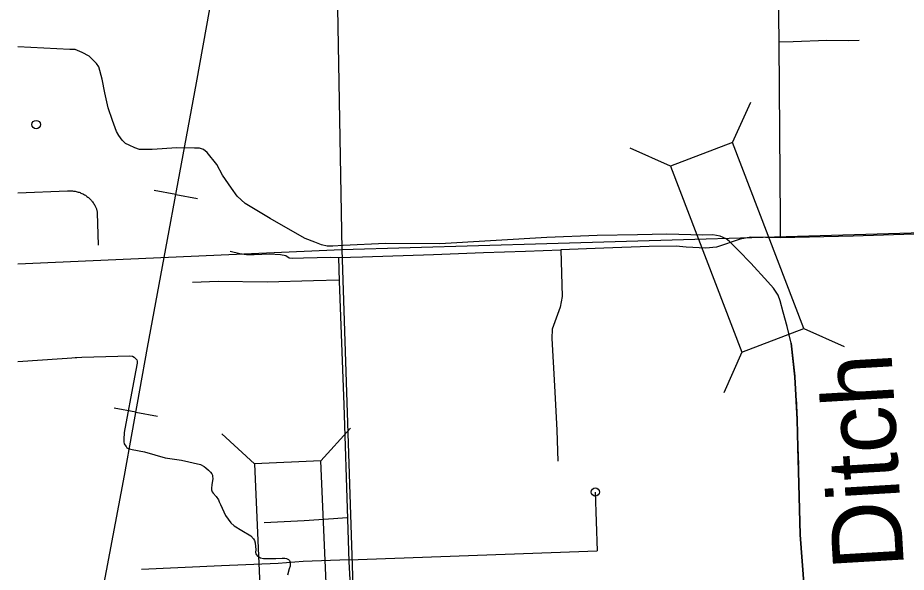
# Model space of a CAD drawing. Extents: x 646058 to 725608, y 1473014 to 1561048.
# Drawn here: x 649176 to 651826, y 1546529 to 1548182 of the extents above; entities that cross this region are included whole.
import ezdxf

# ---------------------------------------------------------------- set-up
doc = ezdxf.new("R2010")
doc.units = 0
doc.layers.add('Default', color=7, linetype='Continuous')

msp = doc.modelspace()

# ---------------------------------------------------------------- linework, layer by layer
at = {"layer": 'Default'}
for p, q in [((651308, 1547810.6), (651361.8, 1547931.1)), ((651123, 1547739.9), (651002.5, 1547793.8)), ((649647.4, 1547655.5), (649582.5, 1547667.6)), ((649647.4, 1547655.5), (649712.2, 1547643.5)), ((651520.1, 1547255.8), (651640.6, 1547201.9)), ((651335.2, 1547185.1), (651281.3, 1547064.6)), ((649528, 1547006.4), (649463, 1547018)), ((649528, 1547006.4), (649593, 1546994.8)), ((649881.8, 1546852.5), (649784.4, 1546941.6)), ((650079.6, 1546861.2), (650168.7, 1546958.6))]:
    msp.add_line(p, q, dxfattribs=at)
for points in [[(649175.8, 1545065), (649314.1, 1545833.5), (649350.5, 1546038), (649406.5, 1546354.4), (649494.3, 1546817.8), (649562.4, 1547199.4), (649709.3, 1547988.3), (649748.7, 1548209.4), (649833.5, 1548683.4), (649871.3, 1548892.3), (649900.1, 1549034.7), (649933.4, 1549177), (649968.2, 1549296.7), (650012.1, 1549423.8), (650066.6, 1549561.6), (650130.2, 1549701), (650202.9, 1549832.7), (650295.2, 1549988.7), (650361.8, 1550099.6)], [(649175.8, 1545065), (649314.1, 1545833.5), (649350.5, 1546038), (649406.5, 1546354.4), (649494.3, 1546817.8), (649562.4, 1547199.4), (649709.3, 1547988.3), (649748.7, 1548209.4), (649833.5, 1548683.4), (649871.3, 1548892.3), (649900.1, 1549034.7), (649933.4, 1549177), (649968.2, 1549296.7), (650012.1, 1549423.8), (650066.6, 1549561.6), (650130.2, 1549701), (650202.9, 1549832.7), (650295.2, 1549988.7), (650361.8, 1550099.6)], [(650076.7, 1550115.4), (650106.2, 1549484.7), (650142.8, 1547491.6)], [(651441.4, 1548452.5), (651445.7, 1548105.6)], [(651441.4, 1548452.5), (651445.7, 1548105.6)], [(649175.8, 1545065), (649314.1, 1545833.5), (649350.5, 1546038), (649406.5, 1546354.4), (649494.3, 1546817.8), (649562.4, 1547199.4), (649709.3, 1547988.3), (649748.7, 1548209.4)], [(651445.6, 1548110.5), (651488.6, 1548112.1), (651588.8, 1548115.4), (651653.6, 1548114.8), (651685.1, 1548115.9)], [(651445.6, 1548110.5), (651488.6, 1548112.1), (651588.8, 1548115.4), (651653.6, 1548114.8), (651685.1, 1548115.9)], [(651482.4, 1547212.5), (651470.3, 1547261.7), (651458.2, 1547304.4), (651449.7, 1547338.6), (651444, 1547355.7), (651429.7, 1547376.3), (651413.4, 1547394.8), (651362.1, 1547451.1), (651325.8, 1547488.9), (651298, 1547516.6), (651288.8, 1547523.8), (651271, 1547530.9), (651248.9, 1547535.1), (651216.9, 1547534.4), (651183.4, 1547535.1), (651111.5, 1547537.3), (651024.7, 1547535.1), (650903.6, 1547533), (650753.4, 1547527.3), (650434.5, 1547508.1), (650272.9, 1547509.5), (650146.2, 1547503.1), (650115.6, 1547501), (650098.5, 1547501), (650082.1, 1547505.9), (650062.2, 1547513.8), (650033, 1547524.5), (649988.8, 1547548.7), (649929, 1547584.3), (649853.6, 1547628.5), (649830.1, 1547650.5), (649813.7, 1547674.7), (649786, 1547713.2), (649769.6, 1547745.3), (649740.4, 1547780.2), (649729.7, 1547789.4), (649718.3, 1547793.7), (649702.7, 1547793.7), (649650.7, 1547795.1), (649576.7, 1547790.1), (649538.9, 1547790.1), (649525.4, 1547794.4), (649507.6, 1547802.2), (649497.6, 1547807.9), (649487.7, 1547817.2), (649477, 1547831.4), (649470.6, 1547843.5), (649458.5, 1547875.6), (649445.7, 1547914.1), (649435.7, 1547958.9), (649427.2, 1547999.5), (649417.2, 1548035.8), (649410.8, 1548046.5), (649399.4, 1548056.5), (649389, 1548067.6), (649367.7, 1548079.3), (649347.1, 1548087.8), (649330.8, 1548088), (649175.8, 1548096)], [(651482.4, 1547212.5), (651470.3, 1547261.7), (651458.2, 1547304.4), (651449.7, 1547338.6), (651444, 1547355.7), (651429.7, 1547376.3), (651413.4, 1547394.8), (651362.1, 1547451.1), (651325.8, 1547488.9), (651298, 1547516.6), (651288.8, 1547523.8), (651271, 1547530.9), (651248.9, 1547535.1), (651216.9, 1547534.4), (651183.4, 1547535.1), (651111.5, 1547537.3), (651024.7, 1547535.1), (650903.6, 1547533), (650753.4, 1547527.3), (650434.5, 1547508.1), (650272.9, 1547509.5), (650146.2, 1547503.1), (650115.6, 1547501), (650098.5, 1547501), (650082.1, 1547505.9), (650062.2, 1547513.8), (650033, 1547524.5), (649988.8, 1547548.7), (649929, 1547584.3), (649853.6, 1547628.5), (649830.1, 1547650.5), (649813.7, 1547674.7), (649786, 1547713.2), (649769.6, 1547745.3), (649740.4, 1547780.2), (649729.7, 1547789.4), (649718.3, 1547793.7), (649702.7, 1547793.7), (649650.7, 1547795.1), (649576.7, 1547790.1), (649538.9, 1547790.1), (649525.4, 1547794.4), (649507.6, 1547802.2), (649497.6, 1547807.9), (649487.7, 1547817.2), (649477, 1547831.4), (649470.6, 1547843.5), (649458.5, 1547875.6), (649445.7, 1547914.1), (649435.7, 1547958.9), (649427.2, 1547999.5), (649417.2, 1548035.8), (649410.8, 1548046.5), (649399.4, 1548056.5), (649389, 1548067.6), (649367.7, 1548079.3), (649347.1, 1548087.8), (649330.8, 1548088), (649175.8, 1548096)], [(651445.7, 1548105.6), (651449.6, 1547579.1), (651449.6, 1547526.6)], [(651445.7, 1548105.6), (651449.6, 1547579.1), (651449.6, 1547526.6)], [(649175.8, 1547448.5), (650142.8, 1547491.6), (652791.8, 1547568.9), (652828.4, 1547570), (654920.6, 1547651.9), (655451.2, 1547664.5), (655464.9, 1547665), (658000, 1547762.6)], [(649175.8, 1547660.4), (649324, 1547666.2), (649326.9, 1547666.4), (649329.9, 1547666.5), (649332.8, 1547666.5), (649335.7, 1547666.4), (649338.7, 1547666.2), (649341.6, 1547665.9), (649344.5, 1547665.5), (649347.4, 1547665), (649350.3, 1547664.4), (649353.2, 1547663.7), (649356, 1547662.9), (649358.8, 1547662), (649361.6, 1547661), (649364.3, 1547659.9), (649367, 1547658.7), (649369.7, 1547657.4), (649372.3, 1547656.1), (649374.9, 1547654.6), (649377.4, 1547653.1), (649379.9, 1547651.5), (649382.3, 1547649.7), (649384.6, 1547648), (649386.9, 1547646.1), (649389.1, 1547644.1), (649391.2, 1547642.1), (649393.3, 1547640), (649395.3, 1547637.8), (649397.2, 1547635.6), (649399.1, 1547633.3), (649400.9, 1547630.9), (649402.5, 1547628.5), (649404.1, 1547626), (649405.7, 1547623.5), (649407.1, 1547620.9), (649408, 1547619), (649408.8, 1547617.1), (649409.6, 1547615.1), (649410.3, 1547613.1), (649410.9, 1547611.1), (649411.4, 1547609), (649411.9, 1547607), (649412.3, 1547604.9), (649412.7, 1547602.8), (649413, 1547600.7), (649416, 1547504)], [(649175.8, 1547660.4), (649324, 1547666.2), (649326.9, 1547666.4), (649329.9, 1547666.5), (649332.8, 1547666.5), (649335.7, 1547666.4), (649338.7, 1547666.2), (649341.6, 1547665.9), (649344.5, 1547665.5), (649347.4, 1547665), (649350.3, 1547664.4), (649353.2, 1547663.7), (649356, 1547662.9), (649358.8, 1547662), (649361.6, 1547661), (649364.3, 1547659.9), (649367, 1547658.7), (649369.7, 1547657.4), (649372.3, 1547656.1), (649374.9, 1547654.6), (649377.4, 1547653.1), (649379.9, 1547651.5), (649382.3, 1547649.7), (649384.6, 1547648), (649386.9, 1547646.1), (649389.1, 1547644.1), (649391.2, 1547642.1), (649393.3, 1547640), (649395.3, 1547637.8), (649397.2, 1547635.6), (649399.1, 1547633.3), (649400.9, 1547630.9), (649402.5, 1547628.5), (649404.1, 1547626), (649405.7, 1547623.5), (649407.1, 1547620.9), (649408, 1547619), (649408.8, 1547617.1), (649409.6, 1547615.1), (649410.3, 1547613.1), (649410.9, 1547611.1), (649411.4, 1547609), (649411.9, 1547607), (649412.3, 1547604.9), (649412.7, 1547602.8), (649413, 1547600.7), (649416, 1547504)], [(652792.5, 1547570.8), (652659.6, 1547567.4), (652245.9, 1547551.5), (652029.4, 1547542.9), (651667.7, 1547531.3), (651449.6, 1547526.6)], [(652792.5, 1547570.8), (652659.6, 1547567.4), (652245.9, 1547551.5), (652029.4, 1547542.9), (651667.7, 1547531.3), (651449.6, 1547526.6)], [(651449.6, 1547526.6), (651361.9, 1547528.2), (651330.9, 1547522), (651259.5, 1547498.7), (651227.6, 1547495.6), (651169.4, 1547498.7), (651139.9, 1547501), (651059.2, 1547500.2), (650923.4, 1547495.6), (650795.4, 1547490.1)], [(651449.6, 1547526.6), (651361.9, 1547528.2), (651330.9, 1547522), (651259.5, 1547498.7), (651227.6, 1547495.6), (651169.4, 1547498.7), (651139.9, 1547501), (651059.2, 1547500.2), (650923.4, 1547495.6), (650795.4, 1547490.1)], [(649809, 1547486.4), (649838.5, 1547479.6), (649858.5, 1547476.4), (649880.5, 1547476.4), (649926.8, 1547478.5), (649959.9, 1547477), (649975.1, 1547473.3), (649985.7, 1547466.4), (649996.7, 1547465.9), (650028.2, 1547466.4), (650109.2, 1547469.1), (650132.1, 1547467.5)], [(649809, 1547486.4), (649838.5, 1547479.6), (649858.5, 1547476.4), (649880.5, 1547476.4), (649926.8, 1547478.5), (649959.9, 1547477), (649975.1, 1547473.3), (649985.7, 1547466.4), (649996.7, 1547465.9), (650028.2, 1547466.4), (650109.2, 1547469.1), (650132.1, 1547467.5)], [(650132.1, 1547467.5), (650204.3, 1547469.6), (650416.2, 1547476.4), (650564.9, 1547482.2), (650690, 1547486.4), (650795.4, 1547490.1)], [(650132.1, 1547467.5), (650204.3, 1547469.6), (650416.2, 1547476.4), (650564.9, 1547482.2), (650690, 1547486.4), (650795.4, 1547490.1)], [(650142.8, 1547491.6), (650228.4, 1544845.7)], [(650795.4, 1547490.1), (650799.4, 1547351.5), (650793.1, 1547319.1), (650769.7, 1547254.4), (650768.8, 1547225.7), (650776.9, 1547084.6), (650784.1, 1546952.5), (650786.8, 1546860.9)], [(650795.4, 1547490.1), (650799.4, 1547351.5), (650793.1, 1547319.1), (650769.7, 1547254.4), (650768.8, 1547225.7), (650776.9, 1547084.6), (650784.1, 1546952.5), (650786.8, 1546860.9)], [(650132.1, 1547467.5), (650134.3, 1547396.8)], [(650132.1, 1547467.5), (650134.3, 1547396.8)], [(650134.2, 1547399.8), (650057.7, 1547398.2), (649919.4, 1547394), (649773.3, 1547396.1), (649697.1, 1547392.9)], [(650134.2, 1547399.8), (650057.7, 1547398.2), (649919.4, 1547394), (649773.3, 1547396.1), (649697.1, 1547392.9)], [(650134.3, 1547396.8), (650147.9, 1547028), (650159.2, 1546688.1)], [(650134.3, 1547396.8), (650147.9, 1547028), (650159.2, 1546688.1)], [(651482.4, 1547212.5), (651482.4, 1547212.5), (651493.6, 1547114.1)], [(651520.9, 1546483.9), (651509.5, 1546641.3), (651504.5, 1546830.8), (651502.3, 1546901.3), (651500.9, 1546984.6), (651493.8, 1547112.1), (651482.4, 1547212.5), (651482.4, 1547212.5)], [(651482.4, 1547212.5), (651482.4, 1547212.5), (651493.8, 1547112.1), (651500.9, 1546984.6), (651502.3, 1546901.3), (651504.5, 1546830.8), (651509.5, 1546641.3), (651520.9, 1546483.9)], [(649175.8, 1547157.3), (649367, 1547170.5), (649509.9, 1547174.4), (649517.6, 1547173.4), (649522.8, 1547170.2), (649527.7, 1547166), (649530.5, 1547162.8), (649531.6, 1547158.6), (649531.6, 1547152.3), (649523.5, 1547110.9), (649493.4, 1546945.5), (649491.9, 1546925.2), (649492.3, 1546918.5), (649493, 1546912.2), (649495.5, 1546908.7), (649499, 1546903.8), (649501.4, 1546900.6), (649504.9, 1546898.2), (649512.6, 1546896.1), (649517.4, 1546895.1)], [(649175.8, 1547157.3), (649367, 1547170.5), (649509.9, 1547174.4), (649517.6, 1547173.4), (649522.8, 1547170.2), (649527.7, 1547166), (649530.5, 1547162.8), (649531.6, 1547158.6), (649531.6, 1547152.3), (649523.5, 1547110.9), (649493.4, 1546945.5), (649491.9, 1546925.2), (649492.3, 1546918.5), (649493, 1546912.2), (649495.5, 1546908.7), (649499, 1546903.8), (649501.4, 1546900.6), (649504.9, 1546898.2), (649512.6, 1546896.1), (649517.4, 1546895.1)], [(649347.1, 1547169.2), (649367, 1547170.5), (649509.9, 1547174.4), (649517.6, 1547173.4), (649522.8, 1547170.2), (649527.7, 1547166), (649530.5, 1547162.8), (649531.6, 1547158.6), (649531.6, 1547152.5)], [(651497.4, 1547048.3), (651500.9, 1546984.6), (651502.3, 1546901.3), (651503.9, 1546850.4)], [(649517.4, 1546895.1), (649554, 1546888), (649615.4, 1546870.1), (649664.2, 1546863.1)], [(649517.4, 1546895.1), (649554, 1546888), (649615.4, 1546870.1), (649664.2, 1546863.1)], [(649664.2, 1546863.1), (649720.7, 1546850.8), (649731.9, 1546844.4), (649737.2, 1546840.2), (649744.5, 1546833.9), (649750.5, 1546827.2), (649754.7, 1546822.7), (649756.5, 1546818.8), (649756.8, 1546814.6), (649757.5, 1546808.6), (649754.7, 1546790), (649753.7, 1546780.2), (649754, 1546774.9), (649755.4, 1546769.3), (649758.2, 1546764.8), (649767.7, 1546754.9), (649774.4, 1546745.5), (649776.5, 1546739.5), (649780.3, 1546731.4), (649795.1, 1546698.1), (649810.9, 1546676.6), (649821.4, 1546667.2), (649843.8, 1546653.5), (649870.5, 1546637.7), (649879.3, 1546628.6), (649882.1, 1546623.6), (649884.2, 1546617), (649884.5, 1546606.4), (649885.6, 1546597), (649885.2, 1546587.8), (649886.3, 1546584.7), (649887.7, 1546580.8), (649890.8, 1546577.3), (649894.7, 1546575.2), (649900, 1546572.7), (649909.1, 1546570.6), (649931.5, 1546570.6), (649945.6, 1546570.6), (649964.2, 1546571.3), (649972.6, 1546571.3), (649977.5, 1546569.9), (649983.5, 1546567.5), (649986.3, 1546564), (649988, 1546556.9), (649988, 1546551.7), (649988, 1546547.5), (649985.6, 1546539.4), (649980.3, 1546520.4)], [(649664.2, 1546863.1), (649720.7, 1546850.8), (649731.9, 1546844.4), (649737.2, 1546840.2), (649744.5, 1546833.9), (649750.5, 1546827.2), (649754.7, 1546822.7), (649756.5, 1546818.8), (649756.8, 1546814.6), (649757.5, 1546808.6), (649754.7, 1546790), (649753.7, 1546780.2), (649754, 1546774.9), (649755.4, 1546769.3), (649758.2, 1546764.8), (649767.7, 1546754.9), (649774.4, 1546745.5), (649776.5, 1546739.5), (649780.3, 1546731.4), (649795.1, 1546698.1), (649810.9, 1546676.6), (649821.4, 1546667.2), (649843.8, 1546653.5), (649870.5, 1546637.7), (649879.3, 1546628.6), (649882.1, 1546623.6), (649884.2, 1546617), (649884.5, 1546606.4), (649885.6, 1546597), (649885.2, 1546587.8), (649886.3, 1546584.7), (649887.7, 1546580.8), (649890.8, 1546577.3), (649894.7, 1546575.2), (649900, 1546572.7), (649909.1, 1546570.6), (649931.5, 1546570.6), (649945.6, 1546570.6), (649964.2, 1546571.3), (649972.6, 1546571.3), (649977.5, 1546569.9), (649983.5, 1546567.5), (649986.3, 1546564), (649988, 1546556.9), (649988, 1546551.7), (649988, 1546547.5), (649985.6, 1546539.4), (649980.3, 1546520.4)], [(651505.7, 1546784.4), (651509.5, 1546641.3), (651513.4, 1546586.6)], [(650898.4, 1546768.5), (650903.8, 1546593.2)], [(650898.4, 1546768.5), (650903.8, 1546593.2)], [(649911.2, 1546677.6), (650030, 1546683.5), (650118, 1546689.8), (650157.1, 1546692.3)], [(650159.2, 1546688.1), (650163.6, 1546560.2)], [(650159.2, 1546688.1), (650163.6, 1546560.2)], [(650163.4, 1546566), (650903.8, 1546593.2)], [(650163.4, 1546566), (650903.8, 1546593.2)], [(650163.4, 1546566), (650026.6, 1546561.4), (649952.3, 1546555), (649783.4, 1546548.6), (649544.5, 1546538)], [(650163.4, 1546566), (650026.6, 1546561.4), (649952.3, 1546555), (649783.4, 1546548.6), (649544.5, 1546538)], [(650163.6, 1546560.2), (650171.2, 1546420.4)], [(650163.6, 1546560.2), (650171.2, 1546420.4)]]:
    msp.add_lwpolyline(points, dxfattribs=at)
for points in [[(651123, 1547739.9), (651335.2, 1547185.1), (651520.1, 1547255.8), (651308, 1547810.6)], [(649881.8, 1546852.5), (649908.1, 1546259), (650105.9, 1546267.8), (650079.6, 1546861.2)]]:
    msp.add_lwpolyline(points, close=True, dxfattribs=at)
for centre in [(649230.7, 1547863.8), (649230.7, 1547863.8), (650898.4, 1546768.5), (650898.4, 1546768.5)]:
    msp.add_circle(centre, 12.5, dxfattribs=at)

# ---------------------------------------------------------------- texts
msp.add_text('Ditch', height=211.2, rotation=93.3676, dxfattribs=at).set_placement((651819.2, 1546544.2))

doc.saveas('drawing.dxf')
